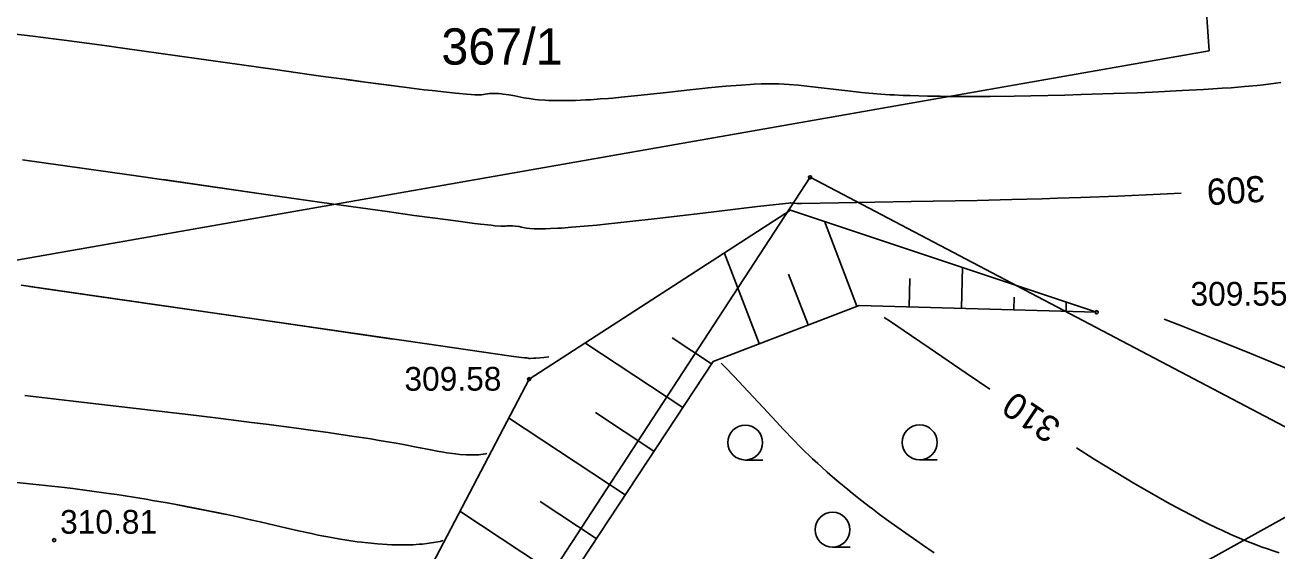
# Model space of a CAD drawing. Extents: x 7477803 to 7478145, y 5500698 to 5500984.
# Drawn here: x 7477865.63 to 7477901.52, y 5500809.46 to 5500824.53 of the extents above; entities that cross this region are included whole.
import ezdxf

# ---------------------------------------------------------------- set-up
doc = ezdxf.new("R2010")
doc.units = 0
for name, color, linetype in [('203-Punkt załamania granicy działki nie stabilizowany', 7, 'Continuous'), ('gr_dzialki', 7, 'Continuous'), ('gr_klasy', 7, 'Continuous'), ('nr_dzialki', 7, 'Continuous'), ('pkt_wys', 7, 'Continuous'), ('skarp_wypel', 7, 'Continuous'), ('skarpa_gora', 7, 'Continuous'), ('warst_ciagla', 7, 'Continuous'), ('warst_opis', 7, 'Continuous'), ('warst_pogrub', 7, 'Continuous'), ('warst_przeryw', 7, 'Continuous'), ('zielen', 7, 'Continuous')]:
    doc.layers.add(name, color=color, linetype=linetype)

# ---------------------------------------------------------------- blocks, each defined once
blk = doc.blocks.new('203')
blk.add_circle((0, 0), 0.045)
blk = doc.blocks.new('801_1')
at = {"layer": 'pkt_wys'}
blk.add_circle((0, 0), 0.045, dxfattribs=at)
blk.add_circle((0, 0), 0.045, dxfattribs=at)
blk = doc.blocks.new('801')
at = {"layer": 'pkt_wys'}
blk.add_circle((0, 0), 0.045, dxfattribs=at)
blk.add_circle((0, 0), 0.045, dxfattribs=at)
blk = doc.blocks.new('941_5')
at = {"layer": 'zielen'}
for p, q in [((-2.5, 0.46), (-2, 0.46)), ((2.5, 0.46), (3, 0.46)), ((0, -2.04), (0.5, -2.04))]:
    blk.add_line(p, q, dxfattribs=at)
for centre in [(-2.503, 0.963), (2.497, 0.963), (-0.003, -1.537)]:
    blk.add_circle(centre, 0.5, dxfattribs=at)

msp = doc.modelspace()

# ---------------------------------------------------------------- linework, layer by layer
at = {"layer": 'gr_dzialki'}
for points in [[(7477888.14, 5500820.17), (7477869.653, 5500791.837)], [(7477904.16, 5500811.76), (7477888.14, 5500820.17)], [(7477904.16, 5500811.76), (7477885.53, 5500801.41)]]:
    msp.add_lwpolyline(points, dxfattribs=at)
at = {"layer": 'gr_klasy'}
for points in [[(7477896.14, 5500873.19), (7477899.58, 5500823.8)], [(7477899.58, 5500823.8), (7477856.78, 5500816.29)], [(7477885.53, 5500801.41), (7477904.16, 5500811.76)]]:
    msp.add_lwpolyline(points, dxfattribs=at)
at = {"layer": 'skarp_wypel'}
for p, q in [((7477889.484, 5500816.478), (7477888.549, 5500818.914)), ((7477886.684, 5500815.403), (7477885.682, 5500818.011)), ((7477892.479, 5500816.417), (7477892.512, 5500817.59)), ((7477888.084, 5500815.941), (7477887.526, 5500817.392)), ((7477890.979, 5500816.46), (7477891.002, 5500817.273)), ((7477893.978, 5500816.375), (7477893.988, 5500816.734)), ((7477895.478, 5500816.332), (7477895.485, 5500816.597)), ((7477884.49, 5500813.573), (7477881.683, 5500815.425)), ((7477885.316, 5500814.824), (7477884.187, 5500815.569)), ((7477882.837, 5500811.069), (7477879.499, 5500813.272)), ((7477883.663, 5500812.321), (7477881.986, 5500813.428)), ((7477882.01, 5500809.817), (7477880.405, 5500810.877)), ((7477881.184, 5500808.565), (7477878.1, 5500810.601))]:
    msp.add_line(p, q, dxfattribs=at)
at = {"layer": 'skarpa_gora'}
for points in [[(7477896.354, 5500816.303), (7477887.581, 5500819.233), (7477880.086, 5500814.385), (7477872.402, 5500799.706), (7477868.556, 5500792.528)], [(7477870.261, 5500791.453), (7477873.595, 5500796.648), (7477880.484, 5500807.495), (7477885.365, 5500814.891), (7477889.544, 5500816.495), (7477896.354, 5500816.303)]]:
    msp.add_lwpolyline(points, dxfattribs=at)
at = {"layer": 'warst_ciagla'}
for points in [[(7477865.56, 5500820.673), (7477866.718, 5500820.513), (7477868.616, 5500820.244), (7477872.472, 5500819.689), (7477874.148, 5500819.449), (7477876.017, 5500819.186), (7477876.795, 5500819.078), (7477877.764, 5500818.947), (7477878.12, 5500818.901), (7477878.521, 5500818.85), (7477878.691, 5500818.83), (7477878.997, 5500818.795), (7477879.111, 5500818.784), (7477879.273, 5500818.771), (7477879.367, 5500818.768), (7477879.404, 5500818.77), (7477879.446, 5500818.778), (7477879.492, 5500818.783), (7477879.569, 5500818.784), (7477879.613, 5500818.781), (7477879.688, 5500818.773), (7477879.802, 5500818.756), (7477879.866, 5500818.744), (7477880.014, 5500818.717), (7477880.11, 5500818.705), (7477880.229, 5500818.697), (7477880.3, 5500818.694), (7477880.378, 5500818.693), (7477880.496, 5500818.694), (7477880.56, 5500818.695), (7477880.7, 5500818.7), (7477880.909, 5500818.71), (7477881.023, 5500818.717), (7477881.303, 5500818.737), (7477881.786, 5500818.777), (7477882.024, 5500818.8), (7477882.364, 5500818.834), (7477882.544, 5500818.852), (7477882.972, 5500818.899), (7477883.668, 5500818.978), (7477885.068, 5500819.145), (7477886.635, 5500819.331), (7477887.433, 5500819.423), (7477887.534, 5500819.433), (7477887.567, 5500819.436), (7477887.593, 5500819.435), (7477887.63, 5500819.431), (7477887.635, 5500819.431)], [(7477869.593, 5500820.104), (7477872.472, 5500819.689), (7477874.148, 5500819.449), (7477876.017, 5500819.186), (7477876.795, 5500819.078), (7477877.764, 5500818.947), (7477878.12, 5500818.901), (7477878.521, 5500818.85), (7477878.691, 5500818.83), (7477878.997, 5500818.795), (7477879.111, 5500818.784), (7477879.273, 5500818.771), (7477879.367, 5500818.768), (7477879.404, 5500818.77), (7477879.446, 5500818.778), (7477879.492, 5500818.783), (7477879.569, 5500818.784), (7477879.613, 5500818.781), (7477879.688, 5500818.773), (7477879.802, 5500818.756), (7477879.866, 5500818.744), (7477880.014, 5500818.717), (7477880.11, 5500818.705), (7477880.229, 5500818.697), (7477880.3, 5500818.694), (7477880.378, 5500818.693), (7477880.496, 5500818.694), (7477880.56, 5500818.695), (7477880.7, 5500818.7), (7477880.909, 5500818.71), (7477881.023, 5500818.717), (7477881.303, 5500818.737), (7477881.786, 5500818.777), (7477882.024, 5500818.8), (7477882.364, 5500818.834), (7477882.544, 5500818.852), (7477882.972, 5500818.899), (7477883.668, 5500818.978), (7477885.068, 5500819.145), (7477886.635, 5500819.331), (7477887.433, 5500819.423), (7477887.534, 5500819.433), (7477887.567, 5500819.436), (7477887.593, 5500819.435), (7477887.63, 5500819.431), (7477887.674, 5500819.426), (7477887.756, 5500819.423), (7477887.892, 5500819.424), (7477888.958, 5500819.439), (7477891.039, 5500819.474), (7477892.928, 5500819.51), (7477893.922, 5500819.532), (7477894.794, 5500819.555), (7477895.231, 5500819.569), (7477895.901, 5500819.591), (7477896.964, 5500819.632), (7477898.173, 5500819.686), (7477898.782, 5500819.716)]]:
    msp.add_lwpolyline(points, dxfattribs=at)
at = {"layer": 'warst_pogrub'}
for points in [[(7477890.263, 5500816.156), (7477890.447, 5500816.033), (7477891.045, 5500815.63), (7477891.551, 5500815.286), (7477892.619, 5500814.556), (7477893.289, 5500814.095)], [(7477865.632, 5500813.912), (7477866.932, 5500813.764), (7477868.825, 5500813.545), (7477870.547, 5500813.339), (7477871.251, 5500813.253), (7477872.131, 5500813.143), (7477872.545, 5500813.09), (7477873.416, 5500812.976), (7477873.819, 5500812.921), (7477874.323, 5500812.851), (7477874.561, 5500812.818), (7477875.008, 5500812.752), (7477875.546, 5500812.67), (7477875.789, 5500812.631), (7477876.274, 5500812.549), (7477876.485, 5500812.51), (7477876.854, 5500812.439), (7477877.267, 5500812.356), (7477877.453, 5500812.32), (7477877.635, 5500812.288), (7477877.727, 5500812.274), (7477877.891, 5500812.251), (7477877.974, 5500812.241), (7477878.098, 5500812.229), (7477878.281, 5500812.216), (7477878.457, 5500812.211), (7477878.541, 5500812.212), (7477878.648, 5500812.217), (7477878.699, 5500812.222), (7477878.772, 5500812.231), (7477878.84, 5500812.243), (7477878.872, 5500812.25)], [(7477865.632, 5500813.912), (7477866.932, 5500813.764), (7477868.825, 5500813.545), (7477870.547, 5500813.339), (7477871.251, 5500813.253), (7477872.131, 5500813.143), (7477872.545, 5500813.09), (7477873.416, 5500812.976), (7477873.683, 5500812.94)], [(7477895.774, 5500812.415), (7477896.285, 5500812.093), (7477896.602, 5500811.897), (7477897.183, 5500811.545), (7477897.448, 5500811.387), (7477897.935, 5500811.104), (7477898.37, 5500810.86), (7477898.634, 5500810.716), (7477898.801, 5500810.626), (7477899.113, 5500810.463), (7477899.358, 5500810.337), (7477899.514, 5500810.26), (7477899.806, 5500810.117), (7477899.944, 5500810.052), (7477900.206, 5500809.932), (7477900.451, 5500809.825), (7477900.607, 5500809.76), (7477900.906, 5500809.642), (7477901.069, 5500809.582), (7477901.28, 5500809.508), (7477901.384, 5500809.474), (7477901.586, 5500809.411)]]:
    msp.add_lwpolyline(points, dxfattribs=at)
at = {"layer": 'warst_przeryw'}
for points in [[(7477901.639, 5500822.886), (7477901.489, 5500822.865), (7477901.14, 5500822.822), (7477900.961, 5500822.803), (7477900.593, 5500822.769), (7477900.212, 5500822.739), (7477899.952, 5500822.721), (7477899.42, 5500822.688), (7477898.803, 5500822.654), (7477897.952, 5500822.613), (7477897.513, 5500822.595), (7477896.841, 5500822.57), (7477895.915, 5500822.541), (7477895.439, 5500822.528), (7477894.473, 5500822.507), (7477893.994, 5500822.499), (7477893.301, 5500822.491), (7477892.654, 5500822.488), (7477892.383, 5500822.489), (7477892.036, 5500822.491), (7477891.87, 5500822.493), (7477891.511, 5500822.498), (7477891.014, 5500822.511), (7477890.809, 5500822.519), (7477890.552, 5500822.531), (7477890.43, 5500822.537), (7477890.171, 5500822.554), (7477889.822, 5500822.582), (7477889.612, 5500822.603), (7477889.226, 5500822.646), (7477888.454, 5500822.734), (7477887.799, 5500822.808), (7477887.537, 5500822.834), (7477887.398, 5500822.844), (7477887.247, 5500822.851), (7477887.164, 5500822.853), (7477887.075, 5500822.853), (7477886.948, 5500822.852), (7477886.881, 5500822.851), (7477886.739, 5500822.846), (7477886.533, 5500822.837), (7477886.424, 5500822.831), (7477886.161, 5500822.814), (7477885.723, 5500822.78), (7477885.512, 5500822.761), (7477885.215, 5500822.732), (7477885.059, 5500822.717), (7477884.693, 5500822.678), (7477884.106, 5500822.613), (7477883.301, 5500822.523), (7477882.911, 5500822.482), (7477882.723, 5500822.464), (7477882.481, 5500822.442), (7477882.363, 5500822.432), (7477882.135, 5500822.415), (7477881.846, 5500822.395), (7477881.708, 5500822.388), (7477881.413, 5500822.375), (7477881.274, 5500822.37), (7477881.096, 5500822.367), (7477881.01, 5500822.367), (7477880.847, 5500822.368), (7477880.644, 5500822.373), (7477880.549, 5500822.378), (7477880.35, 5500822.393), (7477880.259, 5500822.402), (7477880.091, 5500822.425), (7477879.939, 5500822.451), (7477879.676, 5500822.503), (7477879.501, 5500822.534), (7477879.43, 5500822.545), (7477879.339, 5500822.557), (7477879.296, 5500822.562), (7477879.206, 5500822.571), (7477879.084, 5500822.577), (7477879.036, 5500822.577), (7477878.977, 5500822.575), (7477878.95, 5500822.572), (7477878.895, 5500822.564), (7477878.825, 5500822.55), (7477878.779, 5500822.543), (7477878.718, 5500822.538), (7477878.68, 5500822.536), (7477878.585, 5500822.536), (7477878.526, 5500822.538), (7477878.421, 5500822.544), (7477878.295, 5500822.553), (7477878.093, 5500822.57), (7477877.977, 5500822.581), (7477877.717, 5500822.609), (7477877.309, 5500822.655), (7477877.079, 5500822.682), (7477876.499, 5500822.754), (7477875.465, 5500822.889), (7477874.943, 5500822.96), (7477874.185, 5500823.064), (7477873.781, 5500823.12), (7477872.808, 5500823.257), (7477869.531, 5500823.723), (7477868.438, 5500823.876), (7477867.912, 5500823.948), (7477867.405, 5500824.016), (7477866.76, 5500824.1), (7477866.451, 5500824.14), (7477865.859, 5500824.213), (7477865.126, 5500824.3)], [(7477901.639, 5500822.886), (7477901.489, 5500822.865), (7477901.14, 5500822.822), (7477900.961, 5500822.803), (7477900.593, 5500822.769), (7477900.212, 5500822.739), (7477899.952, 5500822.721), (7477899.42, 5500822.688), (7477898.803, 5500822.654), (7477897.952, 5500822.613), (7477897.513, 5500822.595), (7477896.841, 5500822.57), (7477895.915, 5500822.541), (7477895.439, 5500822.528), (7477894.473, 5500822.507), (7477893.994, 5500822.499), (7477893.301, 5500822.491), (7477892.654, 5500822.488), (7477892.383, 5500822.489), (7477892.036, 5500822.491), (7477891.87, 5500822.493), (7477891.511, 5500822.498), (7477891.014, 5500822.511), (7477890.809, 5500822.519), (7477890.552, 5500822.531), (7477890.43, 5500822.537), (7477890.171, 5500822.554), (7477889.822, 5500822.582), (7477889.612, 5500822.603), (7477889.226, 5500822.646), (7477888.454, 5500822.734), (7477887.799, 5500822.808), (7477887.537, 5500822.834), (7477887.398, 5500822.844), (7477887.247, 5500822.851), (7477887.164, 5500822.853), (7477887.075, 5500822.853), (7477886.948, 5500822.852), (7477886.881, 5500822.851), (7477886.739, 5500822.846), (7477886.533, 5500822.837), (7477886.424, 5500822.831), (7477886.161, 5500822.814), (7477885.723, 5500822.78), (7477885.512, 5500822.761), (7477885.215, 5500822.732), (7477885.059, 5500822.717), (7477884.693, 5500822.678), (7477884.106, 5500822.613), (7477883.301, 5500822.523), (7477882.911, 5500822.482), (7477882.723, 5500822.464), (7477882.481, 5500822.442), (7477882.363, 5500822.432), (7477882.135, 5500822.415), (7477881.846, 5500822.395), (7477881.708, 5500822.388), (7477881.413, 5500822.375), (7477881.274, 5500822.37), (7477881.096, 5500822.367), (7477881.01, 5500822.367), (7477880.847, 5500822.368), (7477880.644, 5500822.373), (7477880.549, 5500822.378), (7477880.35, 5500822.393), (7477880.259, 5500822.402), (7477880.091, 5500822.425), (7477879.939, 5500822.451), (7477879.676, 5500822.503), (7477879.501, 5500822.534), (7477879.43, 5500822.545), (7477879.339, 5500822.557), (7477879.296, 5500822.562), (7477879.206, 5500822.571), (7477879.084, 5500822.577), (7477879.036, 5500822.577), (7477878.977, 5500822.575), (7477878.95, 5500822.572), (7477878.895, 5500822.564), (7477878.825, 5500822.55), (7477878.779, 5500822.543), (7477878.718, 5500822.538), (7477878.68, 5500822.536), (7477878.585, 5500822.536), (7477878.526, 5500822.538), (7477878.421, 5500822.544), (7477878.295, 5500822.553), (7477878.093, 5500822.57), (7477877.977, 5500822.581), (7477877.717, 5500822.609), (7477877.309, 5500822.655), (7477877.079, 5500822.682), (7477876.499, 5500822.754), (7477875.994, 5500822.819), (7477875.241, 5500822.919), (7477874.83, 5500822.975)], [(7477876.177, 5500815.534), (7477872.136, 5500816.121), (7477867.702, 5500816.764), (7477865.525, 5500817.078)], [(7477880.654, 5500815.027), (7477880.504, 5500815.01), (7477880.282, 5500814.988), (7477880.209, 5500814.982), (7477880.117, 5500814.979), (7477880.09, 5500814.981), (7477880.056, 5500814.986), (7477880.021, 5500814.991), (7477879.998, 5500814.991), (7477879.955, 5500814.994), (7477879.866, 5500815.005), (7477879.573, 5500815.046), (7477877.09, 5500815.402), (7477872.136, 5500816.121), (7477867.874, 5500816.739), (7477865.765, 5500817.043)], [(7477902.18, 5500814.535), (7477901.19, 5500814.946), (7477900.636, 5500815.173), (7477899.742, 5500815.534), (7477898.789, 5500815.913), (7477898.295, 5500816.107)], [(7477891.702, 5500809.411), (7477891.366, 5500809.635), (7477891.202, 5500809.746), (7477890.881, 5500809.968), (7477890.468, 5500810.262), (7477890.268, 5500810.408), (7477890.12, 5500810.518), (7477889.927, 5500810.663), (7477889.832, 5500810.735), (7477889.622, 5500810.898), (7477889.351, 5500811.114), (7477889.219, 5500811.221), (7477888.962, 5500811.435), (7477888.85, 5500811.53), (7477888.705, 5500811.656), (7477888.633, 5500811.718), (7477888.475, 5500811.859), (7477888.36, 5500811.965), (7477888.209, 5500812.105), (7477888.136, 5500812.175), (7477887.974, 5500812.331), (7477887.868, 5500812.435), (7477887.663, 5500812.643), (7477887.366, 5500812.953), (7477887.174, 5500813.158), (7477886.794, 5500813.569), (7477886.232, 5500814.175), (7477885.964, 5500814.46), (7477885.712, 5500814.722), (7477885.594, 5500814.843)], [(7477877.624, 5500809.757), (7477877.532, 5500809.736), (7477877.471, 5500809.723), (7477877.346, 5500809.701), (7477877.154, 5500809.673), (7477877.025, 5500809.659), (7477876.937, 5500809.651), (7477876.76, 5500809.64), (7477876.559, 5500809.633), (7477876.423, 5500809.632), (7477876.332, 5500809.633), (7477876.149, 5500809.638), (7477876.012, 5500809.644), (7477875.736, 5500809.663), (7477875.461, 5500809.69), (7477875.279, 5500809.711), (7477875.158, 5500809.726), (7477874.918, 5500809.761), (7477874.619, 5500809.809), (7477874.423, 5500809.843), (7477874.038, 5500809.917), (7477873.848, 5500809.957), (7477873.473, 5500810.038), (7477873.103, 5500810.122), (7477872.615, 5500810.236), (7477872.372, 5500810.292), (7477872.099, 5500810.354), (7477871.735, 5500810.434), (7477871.553, 5500810.473), (7477871.19, 5500810.55), (7477870.706, 5500810.648), (7477870.464, 5500810.695), (7477869.921, 5500810.797), (7477869.649, 5500810.846), (7477869.288, 5500810.909), (7477869.107, 5500810.94), (7477868.746, 5500810.999), (7477868.265, 5500811.074), (7477868.025, 5500811.11), (7477867.485, 5500811.186), (7477867.005, 5500811.249), (7477866.765, 5500811.279), (7477866.404, 5500811.321), (7477865.859, 5500811.379), (7477865.307, 5500811.429)], [(7477871.353, 5500810.516), (7477870.875, 5500810.614), (7477870.239, 5500810.738), (7477869.921, 5500810.797), (7477869.649, 5500810.846), (7477869.288, 5500810.909), (7477869.107, 5500810.94), (7477868.746, 5500810.999), (7477868.265, 5500811.074), (7477868.025, 5500811.11), (7477867.485, 5500811.186), (7477867.005, 5500811.249), (7477866.765, 5500811.279), (7477866.404, 5500811.321), (7477865.859, 5500811.379), (7477865.307, 5500811.429)]]:
    msp.add_lwpolyline(points, dxfattribs=at)

# ---------------------------------------------------------------- block references
at = {"layer": '203-Punkt załamania granicy działki nie stabilizowany'}
msp.add_blockref('203', (7477888.14, 5500820.17), dxfattribs=at)
at = {"layer": 'pkt_wys', "rotation": 0.0626175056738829}
for name, p in [('801_1', (7477896.354, 5500816.303)), ('801', (7477880.086, 5500814.385)), ('801', (7477866.471, 5500809.77))]:
    msp.add_blockref(name, p, dxfattribs=at)
at = {"layer": 'zielen', "rotation": 0.0626175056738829}
msp.add_blockref('941_5', (7477888.785, 5500811.607), dxfattribs=at)

# ---------------------------------------------------------------- texts
at = {"layer": 'nr_dzialki'}
msp.add_text('367/1', height=1.04, dxfattribs=at).set_placement((7477877.569, 5500823.4))
at = {"layer": 'pkt_wys'}
for s, p in [('309.55', (7477899.046, 5500816.49)), ('309.58', (7477876.511, 5500814.053)), ('310.81', (7477866.64, 5500809.954))]:
    msp.add_text(s, height=0.68, rotation=0.0626, dxfattribs=at).set_placement(p)
at = {"layer": 'warst_opis'}
for s, rotation, p in [('309', 183.5642, (7477901.163, 5500820.221)), ('310', 145.9383, (7477895.383, 5500813.132))]:
    msp.add_text(s, height=0.75, rotation=rotation, dxfattribs=at).set_placement(p)

doc.saveas('drawing.dxf')
